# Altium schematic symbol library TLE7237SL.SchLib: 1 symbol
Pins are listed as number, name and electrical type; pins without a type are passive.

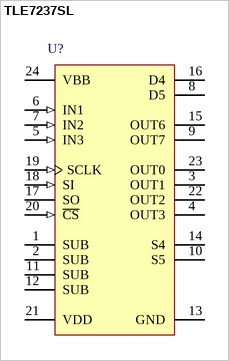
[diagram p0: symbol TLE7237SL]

## TLE7237SL
designator U?
SPI Driver for Enhanced Relay Control, 10 uA Quiescent Current, 3 to 5.5 V VDD, -40 to 150 degC, PG-SSOP-24-5, Reel, Green; Manufacturer: Infineon; PartNumber: TLE7237SL; Channels: 8; Configurable channels: 2; Cranking mode: FALSE; Daisy-chain capability: TRUE; ID nom: 260 mA; ID(lim) (min): 0.5 A; Open Load Detection: off; Overcurrent limitation or shutdown: Shutdown; PWM Inputs: 3; Quiescent Current (max): 10 uA; RDS (on) (max): 1.9 Ohm; RDS (on) (typ): 0.9 Ohm; SPI: 8 Bit; VDD: 3 - 5.5 V; VDS(CL): 41 - 52 V
footprint INF-PG-SSOP-24-5_N (SOP, 24-Leads, Body 8.65x3.9mm, Pitch 0.65mm, IPC Medium Density)
footprint INF-PG-SSOP-24-5_L (SOP, 24-Leads, Body 8.65x3.9mm, Pitch 0.65mm, IPC High Density)
footprint INF-PG-SSOP-24-5_M (SOP, 24-Leads, Body 8.65x3.9mm, Pitch 0.65mm, IPC Low Density)
pins: 1 SUB "Substrate pins for thermal connection. To enable reverse polarity protection these pins must be floating", 2 SUB "Substrate pins for thermal connection. To enable reverse polarity protection these pins must be floating", 3 OUT1 (power) "Source of high side power transistor channel 1", 4 OUT3 (power) "Source of high side power transistor channel 3", 5 IN3 (in) "Input multiplexer input 3 pin (pull down)", 6 IN1 (in) "Input multiplexer input 1 pin (pull down)", 7 IN2 (in) "Input multiplexer input 2 pin (pull down)", 8 D5 (power) "Drain of auto configuring power transistor 5", 9 OUT7 (power) "Drain of low side power transistor channel 7", 10 S5 (power) "Source of auto con?guring power transistor 5", 11 SUB "Substrate pins for thermal connection. To enable reverse polarity protection these pins must be floating", 12 SUB "Substrate pins for thermal connection. To enable reverse polarity protection these pins must be floating", 13 GND (power) "Digital, analog and power ground", 14 S4 (power) "Source of auto configuring power transistor 4", 15 OUT6 (power) "Drain of low side power transistor channel 6", 16 D4 (power) "Drain of auto con?guring power transistor 4", 17 SO (hiz) "Serial data out", 18 SI (in) "Serial data in.", 19 SCLK (in) "Serial clock.", 20 ~{CS} (in) "SPI Chip select (pull up)", 21 VDD (power) "Digital power supply", 22 OUT2 (power) "Source of high side power transistor channel 2", 23 OUT0 (power) "Source of high side power transistor channel 0", 24 VBB (power) "Power supply"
